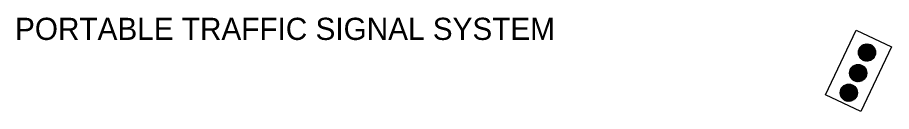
# Model space of a CAD drawing. Extents: x 1678017 to 1687792, y 404433 to 413488.
# Drawn here: x 1684123 to 1684359, y 408407.9 to 408433.4 of the extents above; entities that cross this region are included whole.
import ezdxf

# ---------------------------------------------------------------- set-up
doc = ezdxf.new("R2010")
doc.units = 0
doc.layers.add('Default', color=7, linetype='Continuous')

msp = doc.modelspace()

# ---------------------------------------------------------------- linework, layer by layer
at = {"layer": 'Default'}
for p, q in [((1684350.25, 408424.78), (1684353.49, 408425.94)), ((1684350.31, 408424.91), (1684353.37, 408426.01)), ((1684350.38, 408425.04), (1684353.23, 408426.06)), ((1684350.47, 408425.18), (1684353.08, 408426.12)), ((1684350.58, 408425.33), (1684352.9, 408426.16)), ((1684350.71, 408425.48), (1684352.7, 408426.2)), ((1684350.89, 408425.66), (1684352.45, 408426.21)), ((1684351.18, 408425.87), (1684352.09, 408426.19)), ((1684350.08, 408424.08), (1684354.08, 408425.51)), ((1684350.08, 408423.97), (1684354.15, 408425.43)), ((1684350.08, 408423.86), (1684354.22, 408425.34)), ((1684350.08, 408423.75), (1684354.28, 408425.26)), ((1684350.09, 408424.19), (1684354, 408425.59)), ((1684350.09, 408423.65), (1684354.34, 408425.17)), ((1684350.1, 408423.54), (1684354.4, 408425.08)), ((1684350.11, 408424.3), (1684353.91, 408425.66)), ((1684350.12, 408423.44), (1684354.45, 408425)), ((1684350.14, 408424.42), (1684353.82, 408425.74)), ((1684350.14, 408423.34), (1684354.5, 408424.9)), ((1684350.17, 408424.54), (1684353.72, 408425.81)), ((1684350.17, 408423.25), (1684354.54, 408424.81)), ((1684350.2, 408423.15), (1684354.58, 408424.72)), ((1684350.21, 408424.66), (1684353.61, 408425.88)), ((1684350.23, 408423.05), (1684354.61, 408424.62)), ((1684350.27, 408422.96), (1684354.64, 408424.53)), ((1684350.31, 408422.87), (1684354.67, 408424.43)), ((1684350.36, 408422.78), (1684354.69, 408424.33)), ((1684350.41, 408422.69), (1684354.71, 408424.23)), ((1684350.46, 408422.6), (1684354.72, 408424.12)), ((1684350.52, 408422.51), (1684354.73, 408424.02)), ((1684350.59, 408422.43), (1684354.73, 408423.91)), ((1684350.66, 408422.35), (1684354.73, 408423.81)), ((1684350.73, 408422.27), (1684354.72, 408423.7)), ((1684350.81, 408422.19), (1684354.71, 408423.58)), ((1684350.9, 408422.11), (1684354.69, 408423.47)), ((1684350.99, 408422.04), (1684354.67, 408423.35)), ((1684351.09, 408421.96), (1684354.64, 408423.23)), ((1684351.2, 408421.89), (1684354.6, 408423.11)), ((1684351.31, 408421.83), (1684354.55, 408422.99)), ((1684351.44, 408421.77), (1684354.49, 408422.86)), ((1684351.58, 408421.71), (1684354.42, 408422.73)), ((1684351.73, 408421.66), (1684354.34, 408422.59)), ((1684351.91, 408421.61), (1684354.23, 408422.44)), ((1684352.11, 408421.58), (1684354.1, 408422.29)), ((1684352.36, 408421.56), (1684353.92, 408422.11)), ((1684352.72, 408421.58), (1684353.62, 408421.9)), ((1684347.68, 408418.39), (1684351.75, 408419.85)), ((1684347.68, 408418.29), (1684351.82, 408419.77)), ((1684347.68, 408418.18), (1684351.89, 408419.69)), ((1684347.69, 408418.5), (1684351.68, 408419.93)), ((1684347.69, 408418.07), (1684351.95, 408419.6)), ((1684347.7, 408418.62), (1684351.6, 408420.01)), ((1684347.7, 408417.97), (1684352, 408419.51)), ((1684347.72, 408418.73), (1684351.51, 408420.09)), ((1684347.72, 408417.87), (1684352.05, 408419.42)), ((1684347.74, 408418.85), (1684351.42, 408420.16)), ((1684347.74, 408417.77), (1684352.1, 408419.33)), ((1684347.77, 408418.96), (1684351.32, 408420.24)), ((1684347.77, 408417.67), (1684352.14, 408419.24)), ((1684347.8, 408417.58), (1684352.18, 408419.15)), ((1684347.81, 408419.09), (1684351.21, 408420.3)), ((1684347.83, 408417.48), (1684352.22, 408419.05)), ((1684347.86, 408419.21), (1684351.1, 408420.37)), ((1684347.87, 408417.39), (1684352.25, 408418.95)), ((1684347.91, 408417.29), (1684352.27, 408418.86)), ((1684347.92, 408419.34), (1684350.97, 408420.43)), ((1684347.99, 408419.47), (1684350.83, 408420.49)), ((1684348.07, 408419.61), (1684350.68, 408420.54)), ((1684348.18, 408419.76), (1684350.5, 408420.59)), ((1684348.31, 408419.91), (1684350.3, 408420.62)), ((1684348.49, 408420.08), (1684350.05, 408420.64)), ((1684348.78, 408420.29), (1684349.69, 408420.62)), ((1684347.96, 408417.2), (1684352.29, 408418.76)), ((1684348.01, 408417.11), (1684352.31, 408418.65)), ((1684348.07, 408417.03), (1684352.32, 408418.55)), ((1684348.13, 408416.94), (1684352.33, 408418.45)), ((1684348.19, 408416.86), (1684352.33, 408418.34)), ((1684348.26, 408416.77), (1684352.33, 408418.23)), ((1684348.33, 408416.69), (1684352.33, 408418.12)), ((1684348.41, 408416.61), (1684352.32, 408418.01)), ((1684348.5, 408416.54), (1684352.3, 408417.9)), ((1684348.59, 408416.46), (1684352.27, 408417.78)), ((1684348.69, 408416.39), (1684352.24, 408417.66)), ((1684348.8, 408416.32), (1684352.2, 408417.54)), ((1684348.92, 408416.26), (1684352.16, 408417.42)), ((1684349.04, 408416.19), (1684352.1, 408417.29)), ((1684349.18, 408416.14), (1684352.03, 408417.15)), ((1684349.34, 408416.08), (1684351.94, 408417.02)), ((1684349.51, 408416.04), (1684351.83, 408416.87)), ((1684349.71, 408416), (1684351.7, 408416.71)), ((1684349.96, 408415.99), (1684351.52, 408416.54)), ((1684345.16, 408413.02), (1684349.27, 408414.49)), ((1684345.16, 408412.91), (1684349.34, 408414.41)), ((1684345.17, 408413.13), (1684349.2, 408414.57)), ((1684345.17, 408412.81), (1684349.4, 408414.32)), ((1684345.18, 408413.24), (1684349.12, 408414.65)), ((1684345.18, 408412.7), (1684349.46, 408414.24)), ((1684345.19, 408413.35), (1684349.04, 408414.73)), ((1684345.19, 408412.6), (1684349.51, 408414.15)), ((1684345.21, 408413.47), (1684348.95, 408414.81)), ((1684345.24, 408413.59), (1684348.85, 408414.88)), ((1684345.28, 408413.71), (1684348.75, 408414.95)), ((1684345.32, 408413.83), (1684348.63, 408415.02)), ((1684345.37, 408413.96), (1684348.51, 408415.08)), ((1684345.44, 408414.09), (1684348.38, 408415.14)), ((1684345.52, 408414.22), (1684348.23, 408415.2)), ((1684345.61, 408414.37), (1684348.07, 408415.25)), ((1684345.73, 408414.52), (1684347.88, 408415.29)), ((1684345.89, 408414.68), (1684347.65, 408415.31)), ((1684346.12, 408414.87), (1684347.36, 408415.31)), ((1684350.32, 408416.01), (1684351.23, 408416.33)), ((1684345.21, 408412.5), (1684349.56, 408414.06)), ((1684345.24, 408412.4), (1684349.6, 408413.97)), ((1684345.26, 408412.3), (1684349.64, 408413.87)), ((1684345.3, 408412.21), (1684349.68, 408413.78)), ((1684345.33, 408412.11), (1684349.71, 408413.68)), ((1684345.37, 408412.02), (1684349.74, 408413.59)), ((1684345.42, 408411.93), (1684349.77, 408413.49)), ((1684345.47, 408411.84), (1684349.79, 408413.39)), ((1684345.52, 408411.75), (1684349.8, 408413.28)), ((1684345.58, 408411.66), (1684349.81, 408413.18)), ((1684345.64, 408411.58), (1684349.82, 408413.08)), ((1684345.7, 408411.49), (1684349.82, 408412.97)), ((1684345.85, 408411.33), (1684349.81, 408412.75)), ((1684345.94, 408411.25), (1684349.79, 408412.64)), ((1684346.03, 408411.18), (1684349.77, 408412.52)), ((1684346.12, 408411.11), (1684349.74, 408412.4)), ((1684346.22, 408411.04), (1684349.71, 408412.28)), ((1684346.34, 408410.97), (1684349.67, 408412.16)), ((1684346.46, 408410.9), (1684349.61, 408412.03)), ((1684346.59, 408410.84), (1684349.55, 408411.9)), ((1684346.73, 408410.79), (1684349.47, 408411.77)), ((1684346.9, 408410.74), (1684349.38, 408411.63)), ((1684347.08, 408410.7), (1684349.26, 408411.48)), ((1684347.3, 408410.67), (1684349.11, 408411.32)), ((1684347.58, 408410.66), (1684348.9, 408411.13)), ((1684348.13, 408410.75), (1684348.42, 408410.85))]:
    msp.add_line(p, q, dxfattribs=at)
msp.add_lwpolyline([(1684349.51, 408429.94), (1684359.02, 408425.45), (1684350.72, 408407.89), (1684341.21, 408412.38)], close=True, dxfattribs=at)
for centre in [(1684352.4, 408423.89), (1684350.01, 408418.31), (1684347.49, 408412.99)]:
    msp.add_circle(centre, 2.33, dxfattribs=at)

# ---------------------------------------------------------------- texts
msp.add_text('PORTABLE TRAFFIC SIGNAL SYSTEM', height=6, rotation=360, dxfattribs=at).set_placement((1684122.36, 408427.28))

doc.saveas('drawing.dxf')
